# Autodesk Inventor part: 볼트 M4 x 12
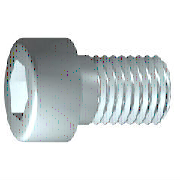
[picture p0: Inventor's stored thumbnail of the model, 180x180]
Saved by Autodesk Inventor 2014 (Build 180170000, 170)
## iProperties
IsCustomPart: 0
Created: 2012-02
Part Number: 볼트 M4 x 12
Material: 강철, 연강
Description: 6각 소켓 머리 캡 나사
Document SubType Name: Modeling
Standard: ISO 4762
Designer: mduedu
Standard Revision: Fourth edition 2004-03-01
Standards Organization: ISO
Language: ko-KR
Size Designation: M4 x 12
Categories: <MemberInstance><Categories><Category DisplayName="조임쇠" InternalName="e4da775c-781d-43d5-af7c-5136215cf5a6" Mnemonic="FSTN"><Category DisplayName="볼트" InternalN
Density: 7.86 g/cm^3
Mass: 2.23465 g
Surface Area: 3.30853 cm^2
Volume: 0.284306 cm^3
Appearance: 강철
Author: mduedu
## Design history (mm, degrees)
sketch "스케치1"
  geometry: L1 (-1, 0)-(12, 0); L2 (12, 0)-(12, 2); L3 (12, 2)-(1.75, 2); L4 (1.75, 2)-(1.32, 2); L5 (1.32, 2)-(0, 2); L6 (0, 2)-(0, 3.5); L7 (0, 3.5)-(-4, 3.5); L8 (-4, 3.5)-(-4, 1.732); L9 (-4, 1.732)-(-2, 1.732); L10 (-2, 1.732)-(-1, 0); L11 (-7.2, 0)-(15.2, 0) reference; L12 (0, -0.7)-(0, 4.2) reference; L13 (1.75, 2)-(0, 2)
  constraints: 22 end point, 6 parallel, 2 collinear, 2 perpendicular, 1 horizontal, 1 point on line
  dimensions: "d1" = 10.25 distance from line of L3.end L2 (= GEL); "d2" = 0.42952 distance of L4.end L3.end (computed from GAL); "d3" = 4 distance between parallel lines of L8 L6 (= KOH); "d4" = 2 distance of L8.end L9.end (= INTI); "d5" = 60 deg angle of L10 L1; "d6" = 4 diameter of L3 L1 (= GD); "d7" = 4 diameter of L5 L1 (= BDM); "d8" = 3.4641 diameter of L9 L1 (= 1.1547 x SW); "d9" = 7 diameter of L7 L1 (= KOD); "d26" = 12 distance between parallel lines of L12 L2 (= NLG)
revolve "본체" sketch "스케치1" stored, may be unused: angle "d10" = 90 deg
sketch "스케치2"
  geometry: L1 (0, -4.9)-(0, 4.9) reference; L2 (-4.9, 0)-(4.9, 0) reference; L3 (1.732, 0)-(0.866, -1.5); L4 (0.866, -1.5)-(-0.866, -1.5); L5 (-0.866, -1.5)-(-1.732, 0); L6 (-1.732, 0)-(-0.866, 1.5); L7 (-0.866, 1.5)-(0.866, 1.5); L8 (0.866, 1.5)-(1.732, 0); 2 further points
  constraints: 12 end point, 1 coincident, 1 horizontal alignment, 1 point on line, 12 other
extrude "슬롯" join sketch "스케치2" stored distance "d11" = 10; taper "d12" = 0 deg
workplane "Work Plane1"
fillet "Fillet2" dims "d30" = 0.1 (= R)
body "Solid1"
fillet "모깎기1" dims "d17" = 0.4 (= RR)
feature "스레드" dims "d13" = 10.25 (= GEL), "d14" = 0
chamfer "모따기1" distance "d15" = 0.42941 (= -0.5 x SPD + 0.5 x GD); stored, may be unused: second distance "d16" = 0.42941 (= GUL), angle "d27" = 45 deg
other parameters: "GD" = 4 [user parameter; used in 2 equation terms], "NLG" = 12 [user parameter; used in 1 equation term], "GEL" = 10.25 [user parameter; used in 2 equation terms], "KOD" = 7 [user parameter; used in 1 equation term], "KOH" = 4 [user parameter; used in 1 equation term], "INTI" = 2 [user parameter; used in 1 equation term], "GAL" = 0.42941 (= 0.61345 x PTC) [user parameter; used in 1 equation term], "GUL" = 0.42941 (= 0.61345 x PTC) [user parameter; used in 1 equation term], "BDM" = 4 (= NND) [user parameter; used in 1 equation term], "SW" = 3 [user parameter; used in 2 equation terms], "RR" = 0.4 [user parameter; used in 1 equation term], "SPD" = 3.14117 (= NND - 1.2269 x PTC) [user parameter; used in 1 equation term], "d19" = 0, "d28" = 0, "d29" = 0, "R" = 0.1 [user parameter; used in 1 equation term], "TOA" = 30 deg [user parameter], "GD1" = 3.14117 (= THREADDIA - 1.2269 x PTC) [user parameter], "THREADDIA" = 4 [user parameter; used in 1 equation term], "FAWI" = 45 deg [user parameter], "TPU" = 14.28571 (computed from PTC) [user parameter], "PTC" = 0.7 [user parameter; used in 5 equation terms], "NND" = 4 [user parameter; used in 2 equation terms], "E0" = 3.465 (= 1.155 x SW) [user parameter]
